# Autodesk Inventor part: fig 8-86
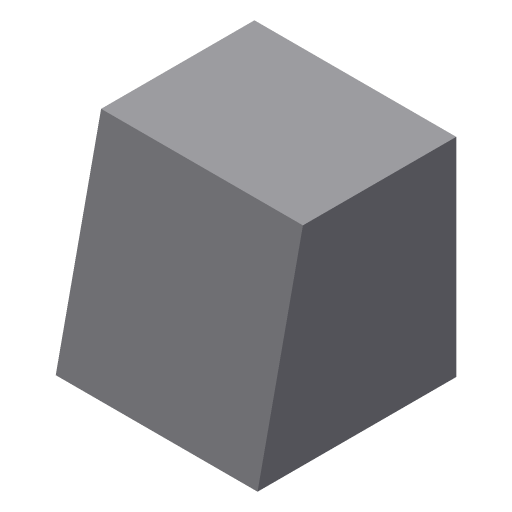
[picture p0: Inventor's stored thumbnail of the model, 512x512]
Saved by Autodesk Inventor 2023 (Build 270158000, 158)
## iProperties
Created: 2009-04
Part Number: fig 8-86
Document SubType Name: Modeling
Designer: Sham
Density: 1 g/cm^3
Material: Generic
Appearance: Default
Author: Sham
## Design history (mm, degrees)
sketch "Sketch5"
  geometry: L1 (14, -14.426)-(0, -14.426); L2 (0, -14.426)-(0, 0); L3 (0, 0)-(14, 0); L4 (14, 0)-(14, -14.426)
  constraints: 8 end point
extrude "Extrusion2" new body sketch "Sketch5" distance "d3" = 20; taper "d4" = 0 deg
sketch "Sketch7"
  geometry: L1 (-2.91, 10)-(18.11, 5.415)
  constraints: 2 end point
split "Split9" sketch "Sketch7"
body "Solid2"
